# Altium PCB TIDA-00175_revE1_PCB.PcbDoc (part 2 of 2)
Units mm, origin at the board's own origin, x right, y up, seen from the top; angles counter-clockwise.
Board outline 109.99 x 49.78 mm, 4 copper layers (Top Layer, mid layer 1-GND, mid layer 2-VCC, Bottom Layer), stack 2.286 mm thick; 124 components, 74 nets, 385 pads, 135 vias.
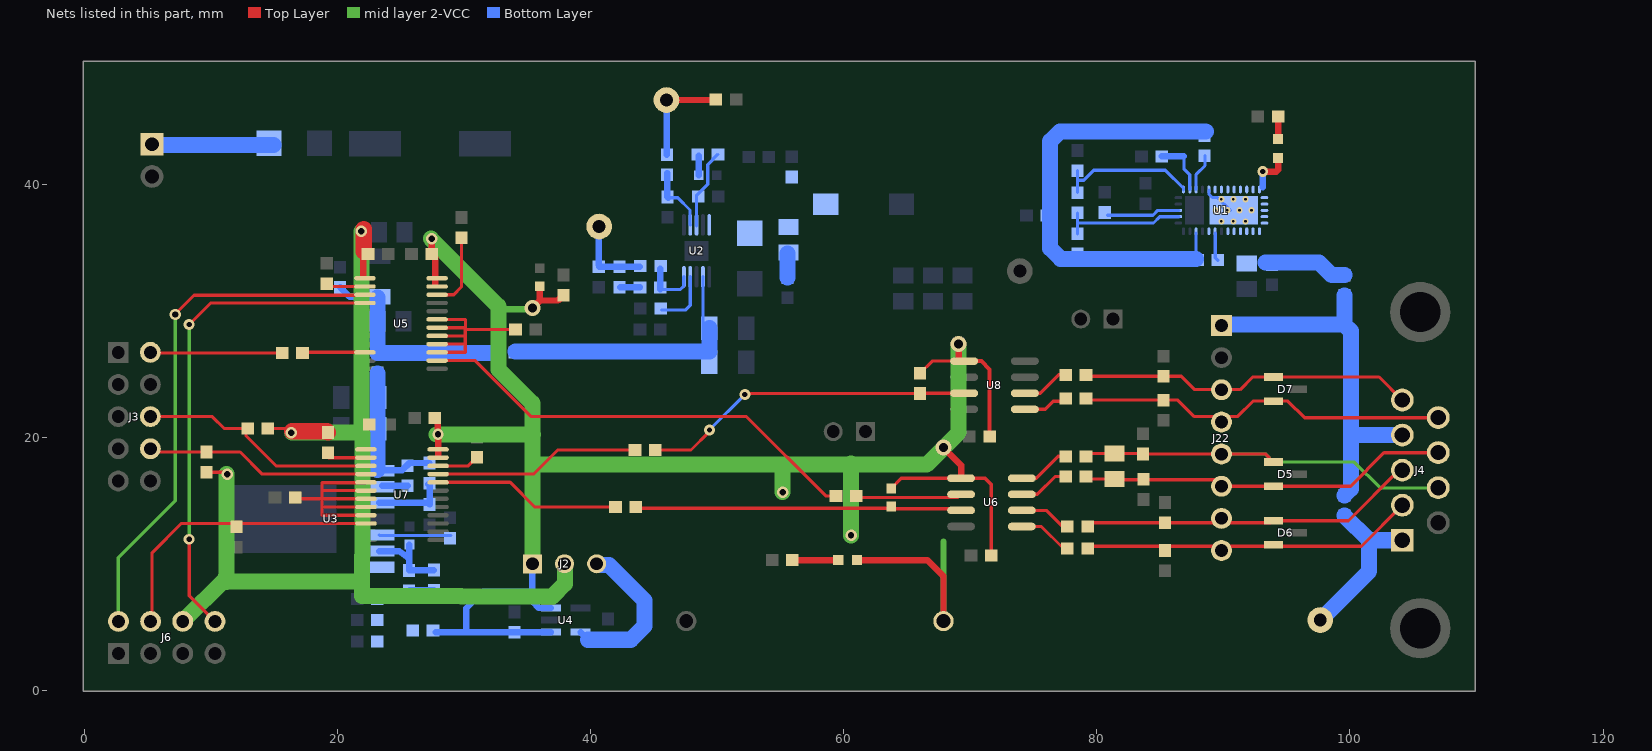
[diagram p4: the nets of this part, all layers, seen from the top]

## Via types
v1: diameter 0.9, hole 0.5, Top Layer to Bottom Layer, 98 vias
v2: diameter 0.5, hole 0.2, Top Layer to Bottom Layer, 19 vias
v3: diameter 1.27, hole 0.711, Top Layer to Bottom Layer, 13 vias
v4: diameter 0.864, hole 0.406, Top Layer to Bottom Layer, 5 vias

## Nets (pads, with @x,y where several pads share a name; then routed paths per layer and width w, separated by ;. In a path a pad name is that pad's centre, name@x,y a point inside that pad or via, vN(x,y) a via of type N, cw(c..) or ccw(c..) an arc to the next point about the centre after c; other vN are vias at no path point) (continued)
NetC9_1: C9.1 L2.2 R10.2 R56.1 R57.2 | length 16.3
  Bottom Layer w0.508: R10.2@20.228,31.836 20.97,31.094 L2.2@23.195,31.094
  Bottom Layer w1.27: R57.2@23.175,26.652 R56.1@32.337,26.652 ; C9.1@23.18,29.171 L2.2@23.18,31.041 ; 23.192,27.218 C9.1@23.192,29.238
NetC10_1: C10.1 C11.1 R56.2 U2.2 | length 21.2
  Bottom Layer w0.254: C11.1@48.884,28.578 U2.2@48.884,32.673
  Bottom Layer w1.27: R56.2@34.068,26.782 C10.1@49.329,26.782 ; C10.1@49.404,26.782 C11.1@49.404,28.611
NetC13_1: C13.1 R13.1 | length 1.9
  Bottom Layer w1.27: C13.1@55.562,32.625 R13.1@55.562,34.504
NetC14_1: C14.1 U2.4 | length 4.6
  Bottom Layer w0.254: C14.1@45.642,30.062 47.533,30.062 47.884,30.413 U2.4@47.884,32.673
NetC15_1: C15.1 R18.1 | length 1.6
  Bottom Layer w0.508: C15.1@42.339,31.847 R18.1@43.915,31.847
NetC15_2: C15.2 R21.1 R22.2 TP3.1 | length 6.3
  Bottom Layer w0.508: R22.2@40.652,33.609 TP3.1@40.652,36.668 ; R22.2@40.696,33.462 R21.1@43.897,33.462
NetC16_1: C16.1 R20.2 U2.8 | length 6.4
  Bottom Layer w0.254: U2.8@48.371,36.696 48.371,39.079 49.273,39.981 49.273,41.543 R20.2@50.073,42.343
NetC17_1: C17.1 R20.1 | length 1.6
  Bottom Layer w0.508: C17.1@48.562,40.692 R20.1@48.562,42.254
NetC18_1: C18.1 C21.1 C22.1 C23.1 R23.1 R25.2 U3.7 | length 1.9
  Bottom Layer w0.508: R25.2@25.716,7.911 C18.1@27.643,7.911
NetC18_2: C18.2 R25.1 R26.2 U3.6 | length 6.5
  Bottom Layer w0.508: U3.6@23.313,11.005 24.892,11.005 25.496,10.568 25.664,10.568 ; R26.2@25.679,11.517 R25.1@25.679,9.474 C18.2@27.606,9.474
NetC19_1: C19.1 C20.1 R24.2 R27.1 R57.1 U3.1 | length 12.1
  Bottom Layer w0.508: U3.1@23.194,17.406 25.141,17.406 25.702,17.967 R24.2@27.28,17.967
  Bottom Layer w1.27: C20.1@23.175,23.183 R57.1@23.175,25.052 ; U3.1@23.194,17.406 C20.1@23.194,23.332
NetC24_1: C24.1 U3.5 | length 5.7
  Bottom Layer w0.254: U3.5@23.313,12.275 23.346,12.242 C24.1@28.976,12.242
NetC26_1: C26.1 J2.3 U4.5 | length 12.5
  Bottom Layer w0.508: U4.5@39.221,4.581 39.802,3.999
  Bottom Layer w1.27: 39.802,3.999 43.185,3.999 44.268,5.083 44.268,7.106 41.474,9.9 J2.3@40.668,9.9
NetC29_2: C29.2 D5.1 J4.7 J22.5 R33.2 R36.2 | length 33.4
  Top Layer w0.254: R33.2@79.153,18.493 79.381,18.721 R36.2@81.407,18.721 83.638,18.721 83.678,18.681 89.845,18.681 93.325,18.681 D5.1@93.967,18.04
  mid layer 2-VCC w0.254: J22.5@89.845,18.681 93.325,18.681 93.967,18.04 100.345,18.04 102.389,15.996 J4.7@106.984,15.996
NetC31_1: C31.1 D5.2 J4.8 J22.6 R36.1 R37.2 | length 29.3
  Top Layer w0.254: R37.2@79.153,16.889 79.353,16.689 R36.1@81.407,16.689 ; R36.1@81.421,16.421 81.637,16.637 89.343,16.637 89.845,16.135 100.06,16.135 102.691,18.766 J4.8@106.984,18.766
NetC32_2: C32.2 D6.2 J4.2 J22.8 R41.2 | length 26.2
  Top Layer w0.254: R41.2@79.297,11.394 C32.2@85.268,11.394 ; C32.2@85.408,11.05 85.747,11.389 100.922,11.389 J4.2@104.144,14.611
NetC33_1: C33.1 D6.1 J4.3 J22.7 R42.2 | length 26.6
  Top Layer w0.254: R42.2@79.28,12.951 79.578,13.25 C33.1@85.408,13.25 93.703,13.25 D6.1@93.846,13.393 ; D6.1@93.967,13.408 99.895,13.408 103.868,17.381 J4.3@104.144,17.381
NetC37_2: C37.2 D7.2 J4.9 J22.4 R52.2 | length 29.8
  Top Layer w0.254: R52.2@79.153,23.058 79.277,22.934 C37.2@85.281,22.934 86.413,22.934 87.719,21.628 89.438,21.628 89.845,21.221 90.251,21.628 91.117,21.628 92.346,22.857 D7.2@93.967,22.857 95.099,22.857 96.42,21.536 J4.9@106.984,21.536
NetC38_1: C38.1 D7.1 J4.5 J22.3 R54.2 | length 26.6
  Top Layer w0.254: R54.2@79.153,24.931 79.273,24.811 C38.1@85.281,24.811 86.695,24.811 87.745,23.761 89.845,23.761 91.325,23.761 92.321,24.757 D7.1@93.967,24.757 102.308,24.757 J4.5@104.144,22.921
NetD1_2: D1.2 R4.2 | length 1.8
  Top Layer w0.508: D1.2@94.335,43.549 R4.2@94.335,45.345
NetD2_2: D2.2 J1.1 | length 9.7
  Bottom Layer w1.27: J1.1@5.274,43.09 10.226,43.09 11.501,43.09 11.493,43.082 D2.2@14.974,43.082
NetD3_1: D3.1 L1.1 R12.2 R13.2 U2.10
NetD4_2: D4.2 R30.2 | length 3.6
  Top Layer w0.508: R30.2@55.955,10.296 D4.2@59.575,10.296
NetJ3_2: J3.2 R40.1 | length 10.4
  Top Layer w0.254: J3.2@5.233,26.708 5.289,26.652 R40.1@15.654,26.652
NetJ3_6: J3.6 R50.2 U7.3 | length 18.9
  Top Layer w0.254: J3.6@5.233,21.628 10.122,21.628 11.049,20.701 R50.2@12.916,20.701 ; R50.2@12.789,20.47 12.789,20.104 15.156,17.737 U7.3@22.262,17.737
NetJ3_8: J3.8 R49.2 U7.4 | length 17.9
  Top Layer w0.254: J3.8@5.233,19.088 5.487,18.834 R49.2@9.652,18.834 12.319,18.834 14.066,17.087 U7.4@22.262,17.087
NetJ4_1: J4.1 R43.2 TP5.1 | length 13.3
  Bottom Layer w1.27: TP5.1@97.663,5.559 101.514,9.41 101.514,11.859 ; R43.2@99.568,13.805 101.514,11.859 ; J4.1@104.142,11.859 101.514,11.859
NetJ4_4: J4.4 J22.1 R43.1 R44.2 | length 30
  Bottom Layer w1.27: J22.1@89.845,28.829 89.916,28.901 99.568,28.901 ; R43.1@99.568,15.405 100.076,15.913 100.076,28.393 99.568,28.901 ; R44.2@99.568,31.204 99.568,28.901 ; 100.076,20.193 J4.4@104.142,20.169
NetJ6_2: J6.2 U5.3 | length 41.1
  Top Layer w0.254: v1@7.158,29.696 8.679,31.217 U5.3@22.023,31.217
  mid layer 2-VCC w0.254: J6.2@2.693,6.162 2.693,10.482 7.201,14.99 v1@7.201,29.863
  other v1: 7.188,29.696
NetJ6_4: J6.4 R55.2 U7.10 | length 22.6
  Top Layer w0.254: J6.4@5.365,6.162 5.365,10.883 7.669,13.187 U7.10@22.262,13.187
NetJ6_8: J6.8 U5.4 | length 38.9
  Top Layer w0.254: v4(8.301,11.938) 8.301,7.485 J6.8@10.333,5.453 ; v4(8.301,28.91) 9.999,30.608 U5.4@22.185,30.608
  mid layer 2-VCC w0.254: v4(8.301,11.938) v4(8.301,28.91)
NetR1_1: R1.1 U1.5 U1.14 U1.15 U1.16 U1.17 U1.18 U1.26 U1.27 U1.38 | length 4.8
  Bottom Layer w0.254: U1.5@88.867,39.534 88.867,39.219 89.143,38.942 89.535,38.942 U1.38@90.555,37.923 ; U1.26@89.361,36.129 89.361,34.187 R1.1@89.562,33.986
  other v2: 89.854,37.048 90.804,37.048 91.754,37.048 89.379,37.923 90.329,37.923 91.279,37.923 92.229,37.923 89.854,38.798 90.804,38.798 91.754,38.798
NetR2_1: R2.1 U1.3 | length 3
  Bottom Layer w0.254: U1.3@87.854,39.573 87.854,40.763 88.554,41.463 R2.1@88.554,42.254
NetR5_2: R5.2 U1.2 | length 4.5
  Bottom Layer w0.254: 86.892,42.183 86.892,41.211 87.354,40.748 U1.2@87.354,39.573
  Bottom Layer w0.508: R5.2@85.125,42.212 86.863,42.212
NetR6_2: R6.2 U1.34 | length 5.8
  Bottom Layer w0.254: R6.2@80.85,37.542 84.444,37.542 84.825,37.923 U1.34@86.505,37.923
NetR7_1: R7.1 R8.2 U1.33 | length 9.9
  Bottom Layer w0.254: R7.1@78.475,36.076 R8.2@78.475,37.725 ; 78.496,36.927 84.485,36.927 84.98,37.423 U1.33@86.505,37.423
NetR8_1: R8.1 R9.2 U1.1 | length 11.1
  Bottom Layer w0.254: R8.1@78.475,39.325 78.475,40.31 ; R9.2@78.475,41.06 78.475,40.31 ; U1.1@86.856,39.56 86.856,39.672 85.431,41.098 79.771,41.098 78.983,40.31 78.475,40.31
NetR16_2: R16.2 R17.2 TP1.1 | length 8
  Top Layer w0.508: TP1.1@46.009,46.641 R16.2@49.75,46.641
  Bottom Layer w0.508: R17.2@46.04,42.329 TP1.1@46.04,46.61
NetR17_1: R17.1 R19.2 U2.7 | length 5.3
  Bottom Layer w0.254: R19.2@46.144,38.916 46.901,38.916 47.864,37.953 47.864,36.793 U2.7@47.884,36.773
  Bottom Layer w0.508: R17.1@46.075,40.873 46.075,38.984 R19.2@46.144,38.916
NetR18_2: R18.2 R21.2 U2.5 | length 4.4
  Bottom Layer w0.254: R18.2@45.516,31.675 47.105,31.675 47.368,31.938 47.368,32.657 U2.5@47.384,32.673
  Bottom Layer w0.508: R18.2@45.516,31.675 R21.2@45.516,33.326
NetR24_1: R24.1 R28.2 U3.3 | length 5.6
  Bottom Layer w0.508: U3.3@23.313,14.815 R28.2@27.187,14.815 ; R24.1@27.192,16.27 R24.1@27.251,16.329 ; R28.2@27.293,14.687 R24.1@27.293,16.287
NetR27_2: R27.2 U3.2 | length 2
  Bottom Layer w0.508: U3.2@23.552,16.158 R27.2@25.551,16.158
NetR31_2: R31.2 U5.2 | length 3.1
  Top Layer w0.254: R31.2@19.168,32.137 19.398,31.908 U5.2@22.185,31.908
NetR32_1: R32.1 U5.22 | length 5.9
  Top Layer w0.254: U5.22@27.885,31.258 29.195,31.258 29.808,31.871 ; 29.814,31.907 R32.1@29.814,35.645
NetR33_1: R33.1 U6.8 | length 4.2
  Top Layer w0.254: U6.8@74.085,16.758 75.23,16.758 76.964,18.493 R33.1@77.553,18.493
NetR37_1: R37.1 U6.7 | length 4
  Top Layer w0.254: U6.7@74.085,15.488 75.305,15.488 76.706,16.889 R37.1@77.553,16.889
NetR38_2: R38.2 U5.15 U5.16 U5.17 U5.18 U5.19 | length 17.7
  Top Layer w0.254: U5.15@27.885,26.708 30.115,26.708 30.115,27.358 ; U5.16@27.885,27.358 30.115,27.358 ; U5.17@27.885,28.008 30.115,28.008 ; U5.18@27.885,28.658 30.124,28.658 30.124,29.308 U5.19@27.885,29.308 ; 30.115,28.515 33.253,28.515 ; 30.115,28.658 30.115,27.358 ; 33.26,28.508 R38.2@34.078,28.508
NetR39_2: R39.2 R47.2 U6.3 | length 25.4
  Top Layer w0.254: R47.2@43.618,14.396 R39.2@63.754,14.396 ; R39.2@64.065,14.345 U6.3@69.285,14.345
NetR40_2: R40.2 U5.10 | length 5
  Top Layer w0.254: R40.2@17.254,26.652 17.31,26.708 U5.10@22.185,26.708
NetR41_1: R41.1 U6.5 | length 4.4
  Top Layer w0.254: U6.5@74.085,12.948 75.634,12.948 77.375,11.207 R41.1@77.68,11.512
NetR42_1: R42.1 U6.6 | length 4.1
  Top Layer w0.254: U6.6@74.085,14.218 76.004,14.218 77.271,12.951 R42.1@77.68,12.951
NetR45_1: R45.1 U7.2 | length 2.9
  Top Layer w0.254: R45.1@19.329,18.387 U7.2@22.262,18.387
NetR46_2: R46.2 U7.22 | length 3.4
  Top Layer w0.254: U7.22@27.962,17.737 30.346,17.737 R46.2@31.03,18.421
NetR47_1: R47.1 U7.20 | length 14.8
  Top Layer w0.254: U7.20@27.962,16.437 33.655,16.437 35.605,14.487 R47.1@41.976,14.487
NetR48_1: R48.1 U7.21 | length 16.4
  Top Layer w0.254: U7.21@27.962,17.087 35.502,17.087 37.408,18.993 R48.1@43.523,18.993
NetR48_2: R48.2 R53.2 U8.3 | length 26.3
  Top Layer w0.254: R48.2@45.123,18.993 47.949,18.993 49.403,20.447 v4(49.403,20.574) ; v4(52.197,23.368) 52.286,23.457 R53.2@66.04,23.457 ; R53.2@66.058,23.475 U8.3@69.524,23.475
  Bottom Layer w0.254: v4(49.403,20.574) v4(52.197,23.368)
NetR51_1: R51.1 U7.5 U7.6 U7.7 U7.8 U7.9 | length 22
  Top Layer w0.254: R51.1@16.682,14.986 16.83,15.134 18.787,15.134 ; 18.879,14.487 U7.8@22.262,14.487 ; U7.5@22.224,16.399 18.787,16.399 18.787,15.787 ; U7.9@22.256,13.843 18.787,13.843 18.787,15.134 ; U7.7@22.262,15.137 18.79,15.137 18.787,15.134 ; U7.6@22.262,15.787 18.787,15.787 ; 18.787,15.134 18.787,15.787
NetR52_1: R52.1 U8.5 | length 3.6
  Top Layer w0.254: U8.5@74.324,22.205 75.931,22.205 76.57,22.844 77.339,22.844 R52.1@77.553,23.058
NetR54_1: R54.1 U8.6 | length 3.8
  Top Layer w0.254: U8.6@74.324,23.475 75.545,23.475 77.001,24.931 R54.1@77.553,24.931
NetR58_1: R58.1 U5.14 | length 35.9
  Top Layer w0.254: U5.14@27.885,26.058 30.907,26.058 35.337,21.628 52.333,21.628 58.594,15.367 R58.1@59.398,15.367
NetR58_2: R58.2 U6.2 | length 8.3
  Top Layer w0.254: R58.2@61.125,15.24 69.037,15.24 U6.2@69.285,15.488
V_ENC: C1.1 C2.1 D1.1 R44.1 U1.6 U1.7 U1.8 U1.9 U1.10 U1.11 U1.12 U1.13 U1.19 U1.20 U1.21 U1.22 U1.23 U1.24 | length 10.1
  Top Layer w0.508: v4(93.118,40.99) 94.176,40.99 94.335,41.148 D1.1@94.335,42.049
  Bottom Layer w0.508: 93.118,39.734 v4(93.118,40.99)
  Bottom Layer w1.27: 93.336,33.804 97.567,33.804 98.566,32.804 R44.1@99.568,32.804
VIO: C27.2 C34.2 J2.2 J6.6 R45.2 R49.1 R50.1 U5.1 U7.1 | length 86.2
  Top Layer w0.254: R49.1@9.652,17.234 11.156,17.234 v1(11.303,17.087) ; R50.1@14.516,20.701 16.206,20.701 v1@16.437,20.47 ; C34.2@22.389,20.727 C34.2@22.559,20.898
  Top Layer w0.508: U5.1@22.058,32.685 C27.2@22.058,34.469 ; C27.2@22.089,34.677 C27.2@22.305,34.461
  Top Layer w1.27: v1@16.437,20.47 19.177,20.47 R45.2@19.27,20.377 ; C27.2@22.089,34.677 v1@22.089,36.443
  mid layer 2-VCC w1.27: J6.6@7.793,5.453 11.176,8.836 11.176,8.922 11.255,9.001 v1@11.255,17.087 ; 11.255,8.582 21.958,8.592 ; v1@16.408,20.391 21.426,20.391 ; v1@21.906,36.244 21.906,20.324 21.98,20.25 21.98,10.65 21.958,10.627 21.958,7.446 29.795,7.446 29.808,7.434 37.004,7.434 37.977,8.407 J2.2@37.977,9.826
  other v1: 16.366,20.355 21.9,36.275
VOUT_5V: R1.2 R2.2 R7.2 R11.2 U1.29 | length 35
  Bottom Layer w0.254: R1.2@87.841,34.096 U1.29@87.841,36.114
  Bottom Layer w1.27: R1.2@87.841,34.096 81.893,34.096 81.886,34.088 80.819,34.088 80.811,34.096 77.139,34.096 76.32,34.914 76.32,43.385 77.104,44.169 R2.2@88.615,44.169
VRS485: C25.1 C28.1 C30.2 C35.1 C36.2 D4.1 J2.1 R23.2 R29.2 R34.1 R35.2 R39.1 R53.1 U4.1 U4.3 U5.23 U5.24 U6.1 U7.23 U7.24 U8.1 | length 166.5
  Top Layer w0.254: R39.1@63.754,15.951 64.561,16.758 U6.1@69.285,16.758 ; R53.1@66.04,25.057 66.998,26.015 U8.1@69.524,26.015
  Top Layer w0.305: U6.1@69.285,16.758 71.164,16.758 71.666,16.256 C30.2@71.666,10.668 ; U8.1@69.524,26.015 70.886,26.015 71.539,25.362 C36.2@71.539,20.066
  Top Layer w0.508: C28.1@27.461,34.461 v1@27.461,35.708 ; U5.23@27.728,32.029 C28.1@27.728,34.195 ; v1@27.944,20.293 C35.1@27.944,21.095 ; U7.23@27.962,18.541 v1@27.962,20.331 ; v3(35.433,30.226) 36.009,30.802 ; R34.1@36.009,31.933 36.009,30.802 ; R35.2@37.854,31.222 37.435,30.802 36.009,30.802 ; D4.1@61.075,10.296 66.613,10.296 67.892,9.017 R29.2@67.892,5.473 ; v3(67.892,19.177) 69.285,17.785 U6.1@69.285,16.758 ; v3(69.088,27.358) 69.088,26.015 U8.1@69.524,26.015
  mid layer 2-VCC w0.508: 33.038,30.368 33.307,30.099 v3@35.129,30.099 ; R29.2@67.892,5.473 67.892,11.737
  mid layer 2-VCC w1.27: v1@27.393,35.688 32.734,30.348 32.734,25.36 35.412,22.682 J2.1@35.412,10 ; v1@27.859,20.231 35.466,20.231 ; 35.938,17.841 66.557,17.841 69.082,20.367 v3@69.082,27.358 ; v1(55.182,15.666) 55.182,17.78 ; v1(60.592,12.249) 60.592,17.907
  Bottom Layer w0.508: R23.2@27.772,4.594 30.198,4.594 ; C25.1@34.004,4.581 U4.1@36.884,4.609 ; C25.1@34.004,4.594 30.198,4.594 ; 35.366,7.798 31.495,7.798 30.198,6.5 30.198,4.594 ; J2.1@35.397,9.95 35.397,7.04 35.928,6.509 U4.3@36.884,6.509
  other v1: 27.956,20.23 27.461,35.68
pads on no net: J3.4 J3.10 J4.10 J4.11 U1.25 U2.6 U4.4 U5.5 U5.6 U5.7 U5.8 U5.9 U7.15 U7.16 U7.17 U7.18 U7.19 U8.2 U8.7 U8.8

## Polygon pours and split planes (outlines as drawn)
VIO on Top Layer "Top Layer-VIO" (solid, remove dead copper, pour order 44): 22.165,18.866 21.454,18.866 20.514,19.806 20.464,19.806 18.787,19.806 18.686,19.907 18.686,20.923 18.686,20.974 19.27,21.558 19.295,21.558 22.902,21.558 22.927,21.558 23.156,21.33 23.156,18.993 23.156,18.967 23.054,18.866
GND_ENC on Top Layer "Top Layer-complet" (solid, pour order 52): 96.11,47.516 96.11,47.567 95.314,48.362 1.372,48.362 0.898,47.888 0.898,1.713 1.541,1.07 95.604,1.07 96.13,1.595
VIO on mid layer 2-VCC "mid layer 2-VCC-angle2" (solid, pour order 36): 20.02,20.812 21.364,22.157 21.892,22.157 21.892,20.523 21.773,20.404 21.722,20.455 20.309,20.455
VIO on mid layer 2-VCC "mid layer 2-VCC-angle1" (solid, pour order 32): 11.533,10.266 12.878,8.922 12.878,8.395 11.244,8.395 11.125,8.514 11.176,8.565 11.176,9.977
VRS485 on mid layer 2-VCC "mid layer 2-VCC-angle1" (solid, pour order 35): 35.736,22.127 38.024,19.839 38.024,19.167 35.788,16.931 35.579,16.931 35.579,17.411 34.636,18.354 32.959,20.031 32.959,20.738 33.597,20.738 34.872,22.013
VRS485 on mid layer 2-VCC "mid layer 2-VCC-angle2" (solid, pour order 38): 59.017,18.815 60.237,17.595 61.086,17.595 62.225,18.734 62.225,19.245 59.296,19.245 59.203,19.152
VRS485 on mid layer 2-VCC "mid layer 2-VCC-angle1" (solid, pour order 40): 69.469,19.939 69.485,20.634 68.636,20.634 67.497,19.495 67.497,18.984 69.082,18.98 69.469,19.423
VIO on mid layer 2-VCC "mid layer 2-VCC-VIO-plane" (solid, pour order 48): 21.775,36.864 23.517,36.864 23.99,36.39 23.99,6.816 23.409,6.234 10.797,6.234 10.078,6.953 10.078,29.144 17.781,36.847
VRS485 on mid layer 2-VCC "mid layer 2-VCC-rs485" (solid, pour order 47): 37.564,11.213 41.598,11.213 42.137,10.674 69.085,10.668 70.231,11.811 70.231,27.813 69.85,28.194 68.326,28.194 64.262,24.13 44.327,24.145 32.136,36.336 26.995,36.336 26.035,35.376 26.035,13.955 28.77,11.219
NetC5_1 on Bottom Layer "Bottom Layer-Vout_8V" (solid, pour order 33): 66.966,32.125 63.76,32.125 63.585,32.297 63.585,40.646 64.074,41.135 74.536,41.132 74.932,40.735 74.932,32.377 74.678,32.128
NetC18_1 on Bottom Layer "Bottom Layer-V33out" (solid, pour order 46): 24.505,10.16 24.523,10.142 24.523,8.646 24.79,8.379 26.126,8.38 26.471,8.035 26.471,3.997 25.866,3.391 24.043,3.391 22.553,3.396 22.557,8.832 22.557,9.439
NetD3_1 on Bottom Layer "Top Layer-SW8" (solid, pour order 45): 59.56,38.787 59.56,40.184 59.56,40.565 58.925,41.2 58.908,41.217 53.007,41.217 52.847,41.217 52.575,40.946 52.575,39.93 52.575,39.676 50.924,38.025 50.797,37.898 50.67,37.771 49.527,37.771 49.4,37.644 49.4,35.993 49.781,35.612 53.972,35.612 58.036,35.612 59.56,37.136
NetR1_1 on Bottom Layer "Top Layer-drain" (solid, pour order 41): 88.813,33.452 89.194,33.071 90.21,33.071 90.464,33.325 90.464,34.595 89.575,35.484 89.575,37.008 89.067,37.008 88.813,36.754
VRS485 on Bottom Layer "Bottom Layer-Vldo1" (solid, pour order 27): 29.553,4.644 30.078,5.169 30.304,5.169 30.722,4.752 30.722,4.573
VRS485 on Bottom Layer "Bottom Layer-vldo2" (solid, pour order 28): 34.867,7.927 35.266,8.327 35.487,8.327 35.583,8.231 35.583,7.575 35.583,7.354 35.272,7.044 35.272,7.235 34.783,7.724
NetC18_2 on Bottom Layer "Bottom Layer-netr15" (solid, pour order 29): 25.192,10.79 25.501,11.099 25.782,11.099 25.782,10.479 25.696,10.393
NetR1_1 on Bottom Layer "Top Layer-Drain" (solid, pour order 42): 92.648,36.78 92.648,39.066 93.553,39.066 93.665,38.953 93.665,36.848 93.597,36.78
V_ENC on Bottom Layer "Bottom Layer-voutfuse small" (solid, pour order 43): 94.549,39.914 94.549,36.08 94.465,35.976 90.1,35.98 90.004,36.266 90.018,36.828 89.168,39.913
V_ENC on Bottom Layer "Bottom Layer-Vnc-capa" (solid, pour order 34): 91.251,33.075 91.096,33.075 91.035,33.156 91.034,33.158 91.034,36.046 91.116,36.156 94.549,36.156 94.549,35.57 94.549,33.157 94.485,33.071
GND_ENC on Bottom Layer "Bottom Layer-complet" (solid, pour order 51): 96.11,47.516 96.11,47.567 95.314,48.362 1.372,48.362 0.898,47.888 0.898,1.713 1.541,1.07 95.604,1.07 96.13,1.595
NetJ4_1 on Bottom Layer "Bottom Layer-NetJ4_sub-d" (solid, pour order 24): 102.87,11.635 102.87,11.491 101.854,10.475 101.219,11.11 101.219,11.303
GND_ENC on mid layer 1-GND "mid layer-complet" (solid, pour order 50): 96.11,47.516 96.11,47.567 95.314,48.362 1.372,48.362 0.898,47.888 0.898,1.713 1.541,1.07 95.604,1.07 96.13,1.595

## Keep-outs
Keep-Out Layer:
  lines w1.2: 110.49,-0.668 -0.079,-0.668 ; 110.516,-0.668 110.516,49.714 ; -0.679,-0.068 ccw(c-0.079,-0.068) -0.079,-0.668 ; -0.679,-0.068 ccw(c-0.079,-0.068) -0.079,-0.668 ; -0.679,-0.068 -0.677,49.714 ; -0.677,49.714 cw(c-0.077,49.714) -0.077,50.314 ; -0.677,49.714 cw(c-0.077,49.714) -0.077,50.314 ; -0.077,50.314 109.916,50.314 ; 109.916,50.314 cw(c109.916,49.714) 110.516,49.714 ; 109.916,50.314 cw(c109.916,49.714) 110.516,49.714

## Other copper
Top Layer:
  pour cut-out: 80.207,12.992 80.01,12.795 80.01,11.938 80.264,11.684 80.303,11.723 89.24,11.723 89.789,12.271 89.789,12.678 89.341,12.678 89.027,12.992
  pour cut-out: 80.137,24.511 79.883,24.257 79.883,23.411 80.053,23.241 80.104,23.292 84.328,23.292 84.328,23.368 84.709,23.749 84.709,24.13 84.328,24.511
  pour cut-out: 84.58,18.439 84.223,18.081 84.223,17.335 84.617,16.941 89.32,16.941 89.94,17.561 89.228,18.273 88.545,18.273
  pour cut-out: 85.852,23.749 86.106,23.495 86.106,23.224 87.322,22.008 89.238,22.008 89.916,22.685 89.171,23.43 87.873,23.43 86.741,24.562 85.892,24.562 85.852,24.522
  pour cut-out: 89.789,12.678 89.789,12.231 90.161,11.859 95.006,11.859 95.117,11.97 95.117,12.871 94.996,12.992 90.394,12.992 90.351,12.948
  pour cut-out: 89.94,17.561 89.94,17.169 90.472,16.637 94.869,16.637 95.117,16.885 95.117,17.34 94.896,17.561 93.091,17.561 92.97,17.681 92.97,18.288 90.551,18.288
  pour cut-out: 89.916,22.685 89.916,22.272 90.217,21.971 91.161,21.971 92.456,23.266 94.995,23.266 95.082,23.353 95.082,24.032 94.816,24.299 92.269,24.299 91.352,23.381 90.634,23.381
  text ".Layer_Name" at -18.849,-40.024 h1.52
mid layer 1-GND:
  text ".Layer_Name" at -18.84,-40.025 h1.52
mid layer 2-VCC:
  text ".Layer_Name" at -18.849,-40.024 h1.52
Bottom Layer:
  pour cut-out: 56.524,34.344 56.524,29.689 56.866,29.346 57.391,29.346 57.734,29.689 57.528,29.894 57.528,33.317 56.593,34.253
  pour cut-out: 54.502,35.101 50.903,35.101 50.786,34.984 50.786,31.406 51.244,30.949 51.244,33.557 51.34,33.653 54.587,33.653 54.587,35.08 54.576,35.09
  text ".Layer_Name" at -18.849,-40.024 h1.52

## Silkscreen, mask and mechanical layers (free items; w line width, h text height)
Top Overlay:
  lines w0.254: 12.489,2.286 12.108,2.667 ; 12.489,3.048 12.108,2.667 ; 13.208,2.667 12.108,2.667 ; 96.119,24.567 96.119,48.132 39.118,48.144 39.118,8.128 96.122,8.128 96.122,11.557 ; 96.121,16.437 96.126,13.187 ; 96.121,21.102 96.122,17.653
  text "24V" at 1.983,46.364 h1.02
  text "GND" at 2.147,36.156 h1.02
  text "Fault" at 3.063,7.572 h1.02 r90
  text "EN" at 5.696,7.572 h1.02 r90
  text "Vio" at 8.258,7.572 h1.02 r90
  text "PG" at 10.75,7.572 h1.02 r90
  text "GND" at 13.589,2.159 h1.02
  text "TIDA-00175 REV E1" at 47.117,1.778 h1.5
  text "V_RS485" at 35.941,0.889 h1.02 r90
  text "V_IO" at 38.481,0.889 h1.02 r90
  text "V_LDO" at 40.894,0.889 h1.02 r90
Bottom Overlay:
  lines w0.254: 96.119,20.987 96.119,48.132 39.118,48.144 39.118,8.128 96.122,8.128 96.122,12.445 ; 96.121,21.09 96.129,12.457
M1 Board Outline:
  the board outline again, w0.254
M5 Assembly Top:
  lines w0.254: -40.922,-41.845 126.718,-41.845 ; -40.922,-36.68 126.769,-36.68 ; -40.922,-31.515 -40.922,-47.009 60.805,-47.009 126.769,-47.009 126.769,-31.515 -40.909,-31.515 -40.909,-47.009 -0.892,-47.009 ; 21.689,-47.009 21.689,-31.515 ; 53.871,-36.68 53.871,-31.515 ; 75.207,-36.68 75.207,-31.515 ; 91.006,-47.174 91.006,-42.022
  text "COMPONENTS MARKED 'DNP' SHOULD NOT BE POPULATED." at -4.206,-26.308 h1.52
  text "ASSEMBLY VARIANT:" at -4.219,-29.242 h1.52
  text ".VariantName" at 22.095,-29.242 h1.52
  text "PCB VIEWED FROM TOP SIDE" at -39.309,-34.872 h1.52
  text "BOARD #:" at 23.594,-34.872 h1.52
  text ".PRJ_Number" at 37.45,-34.872 h1.52
  text "REV:" at 58.9,-34.872 h1.52
  text ".PCB_Rev" at 66.304,-34.872 h1.52
  text "SVN REV:" at 80.185,-34.872 h1.52
  text ".VersionControl_RevNumber" at 93.038,-34.872 h1.52
  text "IGNORE ->" at -39.309,-40.024 h1.52
  text "PLOT NAME =" at -39.309,-45.252 h1.52
  text ".plot_File_Name" at -18.849,-45.252 h1.52
  text "GENERATED    :" at 23.645,-45.252 h1.52
  text ".Print_Date" at 45.73,-45.252 h1.52
  text ".Print_Time" at 64.247,-45.252 h1.52
  text "TEXAS INSTRUMENTS" at 96.365,-45.252 h1.52
M6 Assembly Bottom:
  lines w0.254: -40.935,-36.693 126.756,-36.693 ; -40.884,-41.857 126.756,-41.857 ; -5.172,-47.187 -5.172,-42.035 ; 10.627,-36.693 10.627,-31.528 ; 31.963,-36.693 31.963,-31.528 ; 64.145,-47.022 64.145,-31.528 ; 86.726,-47.022 126.743,-47.022 126.743,-31.528 -40.935,-31.528 -40.935,-47.022 25.029,-47.022 126.756,-47.022 126.756,-31.528
  text "COMPONENTS MARKED 'DNP' SHOULD NOT BE POPULATED." at 121.486,-26.296 h1.52
  text ".VariantName" at 94.968,-29.242 h1.52
  text "ASSEMBLY VARIANT:" at 121.359,-29.242 h1.52
  text ".VersionControl_RevNumber" at -7.204,-34.885 h1.52
  text "SVN REV:" at 5.649,-34.885 h1.52
  text ".PCB_Rev" at 19.53,-34.885 h1.52
  text "REV:" at 26.934,-34.885 h1.52
  text ".PRJ_Number" at 48.384,-34.885 h1.52
  text "BOARD #:" at 62.24,-34.885 h1.52
  text "PCB VIEWED FROM BOTTOM SIDE" at 125.143,-34.885 h1.52
  text "IGNORE ->" at 31.21,-40.024 h1.52
  text "TEXAS INSTRUMENTS" at -10.531,-45.265 h1.52
  text ".Print_Time" at 21.587,-45.265 h1.52
  text ".Print_Date" at 40.104,-45.265 h1.52
  text "GENERATED    :" at 62.189,-45.265 h1.52
  text ".plot_File_Name" at 104.683,-45.265 h1.52
  text "PLOT NAME =" at 125.143,-45.265 h1.52
M9 Title Sheet:
  drawing of 57 lines, arcs and shapes, not listed
  text "1" at -14.713,185.909 h1.78
  text "2" at 48.676,185.909 h1.78
  text "3" at 111.906,185.909 h1.78
  text "4" at 175.575,185.909 h1.78
  text "5" at 239.049,185.909 h1.78
  text "6" at 302.676,185.909 h1.78
  text "A" at 333.563,173.547 h1.78
  text "A" at -44.084,156.877 h1.78
  text "B" at -44.084,96.425 h1.78
  text "B" at 331.836,96.425 h1.78
  text "C" at -44.084,36.1 h1.78
  text "PROJECT TITLE:" at 254.62,-11.17 h1.14
  text ".PRJ_Title" at 255.89,-14.556 h1.78
  text "DESIGNED FOR:" at 254.62,-18.815 h1.14
  text ".PRJ_Customer" at 255.89,-22.371 h1.78
  text "D" at 331.836,-24.098 h1.78
  text "FILE NAME:" at 254.62,-26.435 h1.14
  text ".PCB_File_Name_No_Path" at 255.89,-29.483 h1.78
  text "Texas Instruments (TI) and/or its licensors do not warrant the accuracy or completeness of this specification" at 128.394,-33.594 h1.14
  text "ENGINEER:" at 254.62,-33.801 h1.14
  text "LAYOUT BY:" at 292.847,-33.801 h1.14
  text "or any information contained therein. TI and/or its licensors do not warrant that this design will meet" at 127.252,-36.456 h1.14
  text ".PRJ_Engineer" at 255.89,-37.738 h1.78
  text ".PCB_Layout" at 294.129,-37.738 h1.78
  text "the specifications, will be suitable for your application or fit for any particular purpose, or will operate in" at 127.252,-39.317 h1.14
  text "ALTIUM DESIGNER VERSION:" at 292.847,-41.675 h1.14
  text "an implementation. TI and/or its licensors do not warrant that the design is production worthy. You should" at 127.252,-42.179 h1.14
  text "completely validate and test your design implementation to confirm the system functionality for your application." at 128.394,-45.041 h1.14
  text ".print_Scale" at 255.89,-45.062 h1.78
  text ".Application_BuildNumber" at 294.129,-45.062 h1.78
  text "2" at 48.676,-50.311 h1.78
  text "3" at 111.906,-50.311 h1.78
  text "4" at 175.575,-50.311 h1.78
  text "5" at 239.049,-50.311 h1.78
  text "6" at 302.676,-50.311 h1.78
M11 Gerber Information:
  lines w0.254: -40.922,-41.845 126.718,-41.845 ; -40.922,-36.68 126.769,-36.68 ; -40.922,-31.515 -40.922,-47.009 60.805,-47.009 126.769,-47.009 126.769,-31.515 -40.909,-31.515 -40.909,-47.009 -0.892,-47.009 ; 21.689,-47.009 21.689,-31.515 ; 53.871,-36.68 53.871,-31.515 ; 75.207,-36.68 75.207,-31.515 ; 91.006,-47.174 91.006,-42.022
  text "ALL ARTWORK VIEWED FROM TOP SIDE" at -39.309,-34.872 h1.52
  text "BOARD #:" at 23.594,-34.872 h1.52
  text ".PRJ_Number" at 37.45,-34.872 h1.52
  text "REV:" at 58.9,-34.872 h1.52
  text ".PCB_Rev" at 66.304,-34.872 h1.52
  text "SVN REV:" at 80.185,-34.872 h1.52
  text ".VersionControl_RevNumber" at 93.038,-34.872 h1.52
  text "LAYER NAME =" at -39.309,-40.024 h1.52
  text "PLOT NAME =" at -39.309,-45.252 h1.52
  text ".plot_File_Name" at -18.849,-45.252 h1.52
  text "GENERATED    :" at 23.645,-45.252 h1.52
  text ".Print_Date" at 45.73,-45.252 h1.52
  text ".Print_Time" at 64.247,-45.252 h1.52
  text "TEXAS INSTRUMENTS" at 96.365,-45.252 h1.52

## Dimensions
-0.079,-0.068 to -0.077,49.714 on M2 Board Dimensions
109.916,-0.606 to -0.079,-0.068 on M2 Board Dimensions
96.119,48.132 to 39.118,48.144 on M2 Board Dimensions
96.393,48.133 to 96.647,8.128 on M2 Board Dimensions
